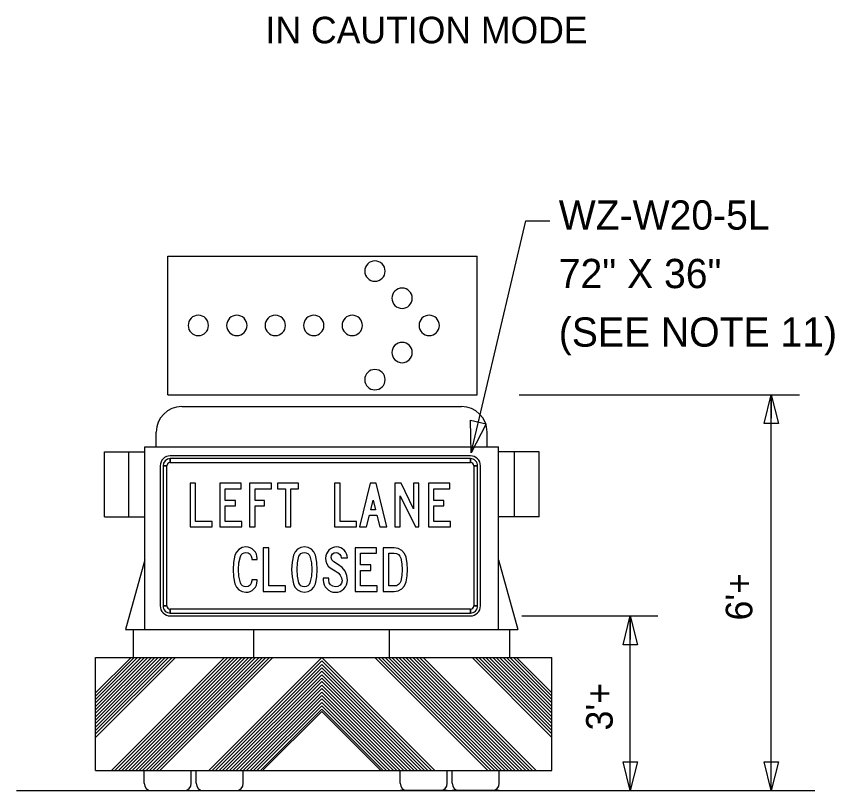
# Model space of a CAD drawing. Extents: x 1806907 to 1812607, y 675071 to 676228.
# Drawn here: x 1811793.7 to 1811978.3, y 675389 to 675563.7 of the extents above; entities that cross this region are included whole.
import ezdxf

# ---------------------------------------------------------------- set-up
doc = ezdxf.new("R2010")
doc.units = 0
doc.layers.add('Working Level 1', color=7, linetype='Continuous')

msp = doc.modelspace()

# ---------------------------------------------------------------- linework, layer by layer
at = {"layer": 'Working Level 1'}
for p, q in [((1811827.84, 675509.6), (1811897.61, 675509.6)), ((1811827.84, 675478.31), (1811827.84, 675509.6)), ((1811897.61, 675478.31), (1811897.61, 675509.6)), ((1811827.84, 675478.31), (1811897.61, 675478.31)), ((1811907.08, 675478.31), (1811970.35, 675478.31)), ((1811963.98, 675389), (1811963.98, 675478.31)), ((1811963.98, 675478.31), (1811963.98, 675473.07)), ((1811830.98, 675475.64), (1811894.12, 675475.64)), ((1811825.24, 675466.6), (1811825.24, 675469.9)), ((1811899.87, 675466.6), (1811899.87, 675469.9)), ((1811822.64, 675425.34), (1811822.64, 675466.6)), ((1811822.64, 675466.6), (1811902.47, 675466.6)), ((1811902.47, 675425.34), (1811902.47, 675466.6)), ((1811813.53, 675465.44), (1811822.64, 675465.44)), ((1811813.53, 675450.77), (1811813.53, 675465.44)), ((1811819.05, 675450.77), (1811819.05, 675465.44)), ((1811896.1, 675464.53), (1811828.38, 675464.53)), ((1811911.58, 675465.44), (1811902.47, 675465.44)), ((1811906.06, 675450.77), (1811906.06, 675465.44)), ((1811911.58, 675450.77), (1811911.58, 675465.44)), ((1811828.38, 675463.03), (1811828.38, 675463.91)), ((1811896.1, 675463.91), (1811896.1, 675463.03)), ((1811826.13, 675462.28), (1811826.13, 675430.68)), ((1811826.75, 675462.28), (1811827.63, 675462.28)), ((1811896.85, 675462.28), (1811897.73, 675462.28)), ((1811898.35, 675430.68), (1811898.35, 675462.28)), ((1811813.53, 675450.77), (1811822.64, 675450.77)), ((1811911.58, 675450.77), (1811902.47, 675450.77)), ((1811822.64, 675441.06), (1811818.32, 675425.34)), ((1811902.47, 675441.06), (1811906.78, 675425.34)), ((1811827.63, 675430.68), (1811826.75, 675430.68)), ((1811828.38, 675429.05), (1811828.38, 675429.92)), ((1811896.1, 675429.92), (1811896.1, 675429.05)), ((1811897.73, 675430.68), (1811896.85, 675430.68)), ((1811828.38, 675428.42), (1811896.1, 675428.42)), ((1811907.73, 675428.42), (1811938.35, 675428.42)), ((1811932.17, 675389), (1811932.17, 675428.42)), ((1811932.17, 675428.42), (1811932.17, 675423.09)), ((1811818.32, 675425.34), (1811906.78, 675425.34)), ((1811820.12, 675419.03), (1811820.12, 675425.34)), ((1811847.24, 675419.03), (1811847.24, 675425.22)), ((1811877.87, 675419.03), (1811877.87, 675425.22)), ((1811904.99, 675419.03), (1811904.99, 675425.34)), ((1811811.55, 675419.03), (1811914.5, 675419.03)), ((1811811.55, 675419.03), (1811914.5, 675419.03)), ((1811811.55, 675419.03), (1811914.5, 675419.03)), ((1811811.55, 675419.03), (1811914.5, 675419.03)), ((1811811.55, 675393.54), (1811811.55, 675419.03)), ((1811811.55, 675411.05), (1811819.53, 675419.03)), ((1811811.55, 675401.78), (1811828.81, 675419.03)), ((1811811.55, 675402.56), (1811828.02, 675419.03)), ((1811811.55, 675403.34), (1811827.24, 675419.03)), ((1811811.55, 675404.11), (1811826.47, 675419.03)), ((1811811.55, 675404.89), (1811825.69, 675419.03)), ((1811811.55, 675405.67), (1811824.91, 675419.03)), ((1811811.55, 675406.44), (1811824.14, 675419.03)), ((1811811.55, 675407.22), (1811823.36, 675419.03)), ((1811811.55, 675408), (1811822.58, 675419.03)), ((1811811.55, 675408.78), (1811821.8, 675419.03)), ((1811811.55, 675409.55), (1811821.03, 675419.03)), ((1811811.55, 675410.33), (1811820.25, 675419.03)), ((1811811.55, 675401), (1811829.56, 675419.01)), ((1811815.14, 675393.54), (1811840.64, 675419.03)), ((1811815.91, 675393.54), (1811841.41, 675419.03)), ((1811816.69, 675393.54), (1811842.19, 675419.03)), ((1811817.48, 675393.54), (1811842.97, 675419.03)), ((1811818.25, 675393.54), (1811843.74, 675419.03)), ((1811819.03, 675393.54), (1811844.52, 675419.03)), ((1811819.81, 675393.54), (1811845.31, 675419.03)), ((1811820.59, 675393.54), (1811846.09, 675419.03)), ((1811821.36, 675393.54), (1811846.86, 675419.03)), ((1811822.14, 675393.54), (1811847.64, 675419.03)), ((1811822.92, 675393.54), (1811848.42, 675419.03)), ((1811823.69, 675393.54), (1811849.19, 675419.03)), ((1811824.47, 675393.54), (1811849.97, 675419.03)), ((1811825.25, 675393.54), (1811850.74, 675419.02)), ((1811826.03, 675393.54), (1811851.53, 675419.03)), ((1811837.06, 675393.54), (1811862.55, 675419.03)), ((1811837.83, 675393.54), (1811862.55, 675418.26)), ((1811888.05, 675393.54), (1811862.55, 675419.03)), ((1811887.24, 675393.58), (1811862.55, 675418.26)), ((1811900.01, 675393.54), (1811874.52, 675419.03)), ((1811900.79, 675393.54), (1811875.3, 675419.02)), ((1811901.57, 675393.54), (1811876.07, 675419.03)), ((1811902.35, 675393.54), (1811876.85, 675419.03)), ((1811903.12, 675393.54), (1811877.62, 675419.03)), ((1811903.9, 675393.54), (1811878.4, 675419.03)), ((1811904.68, 675393.54), (1811879.19, 675419.03)), ((1811905.45, 675393.54), (1811879.96, 675419.03)), ((1811906.23, 675393.54), (1811880.74, 675419.03)), ((1811907.02, 675393.54), (1811881.52, 675419.03)), ((1811907.8, 675393.54), (1811882.3, 675419.03)), ((1811908.57, 675393.54), (1811883.07, 675419.03)), ((1811909.35, 675393.54), (1811883.85, 675419.03)), ((1811910.13, 675393.54), (1811884.63, 675419.03)), ((1811910.9, 675393.54), (1811885.41, 675419.03)), ((1811914.5, 675401), (1811896.48, 675419.01)), ((1811914.5, 675401.78), (1811897.24, 675419.03)), ((1811914.5, 675402.56), (1811898.02, 675419.03)), ((1811914.5, 675403.34), (1811898.8, 675419.03)), ((1811914.5, 675404.11), (1811899.57, 675419.03)), ((1811914.5, 675404.89), (1811900.35, 675419.03)), ((1811914.5, 675405.67), (1811901.13, 675419.03)), ((1811914.5, 675406.44), (1811901.9, 675419.03)), ((1811914.5, 675407.22), (1811902.68, 675419.03)), ((1811914.5, 675408), (1811903.46, 675419.03)), ((1811914.5, 675408.78), (1811904.24, 675419.03)), ((1811914.5, 675409.55), (1811905.01, 675419.03)), ((1811914.5, 675410.33), (1811905.79, 675419.03)), ((1811914.5, 675411.05), (1811906.52, 675419.03)), ((1811914.5, 675393.54), (1811914.5, 675419.03)), ((1811838.61, 675393.54), (1811862.55, 675417.48)), ((1811839.39, 675393.54), (1811862.55, 675416.7)), ((1811886.5, 675393.54), (1811862.55, 675417.48)), ((1811885.72, 675393.54), (1811862.55, 675416.7)), ((1811840.16, 675393.54), (1811862.55, 675415.93)), ((1811840.94, 675393.54), (1811862.55, 675415.15)), ((1811884.95, 675393.54), (1811862.55, 675415.93)), ((1811884.17, 675393.54), (1811862.55, 675415.15)), ((1811841.73, 675393.54), (1811862.55, 675414.37)), ((1811842.5, 675393.54), (1811862.55, 675413.6)), ((1811843.28, 675393.54), (1811862.55, 675412.81)), ((1811883.39, 675393.54), (1811862.55, 675414.37)), ((1811882.62, 675393.54), (1811862.55, 675413.6)), ((1811881.84, 675393.54), (1811862.55, 675412.81)), ((1811844.06, 675393.54), (1811862.55, 675412.03)), ((1811844.84, 675393.54), (1811862.55, 675411.25)), ((1811881.06, 675393.54), (1811862.55, 675412.03)), ((1811880.27, 675393.54), (1811862.55, 675411.25)), ((1811845.61, 675393.54), (1811862.55, 675410.48)), ((1811846.39, 675393.54), (1811862.55, 675409.7)), ((1811879.5, 675393.54), (1811862.55, 675410.48)), ((1811878.72, 675393.54), (1811862.55, 675409.7)), ((1811847.17, 675393.54), (1811862.55, 675408.92)), ((1811847.94, 675393.54), (1811862.55, 675408.15)), ((1811848.72, 675393.54), (1811862.55, 675407.37)), ((1811877.94, 675393.54), (1811862.55, 675408.92)), ((1811877.17, 675393.54), (1811862.55, 675408.15)), ((1811876.39, 675393.54), (1811862.55, 675407.37)), ((1811849.37, 675393.69), (1811862.55, 675406.87)), ((1811875.89, 675393.54), (1811862.55, 675406.87)), ((1811811.55, 675393.54), (1811914.5, 675393.54)), ((1811811.55, 675393.54), (1811914.5, 675393.54)), ((1811811.55, 675393.54), (1811914.5, 675393.54)), ((1811811.55, 675393.54), (1811914.5, 675393.54)), ((1811822.49, 675390.65), (1811822.49, 675393.54)), ((1811833.12, 675390.65), (1811833.12, 675393.54)), ((1811834.22, 675390.65), (1811834.22, 675393.54)), ((1811844.86, 675390.65), (1811844.86, 675393.54)), ((1811880.25, 675390.65), (1811880.25, 675393.54)), ((1811890.88, 675390.65), (1811890.88, 675393.54)), ((1811891.98, 675390.65), (1811891.98, 675393.54)), ((1811902.62, 675390.65), (1811902.62, 675393.54)), ((1811793.67, 675389), (1811973.78, 675389)), ((1811822.49, 675389), (1811833.12, 675389)), ((1811822.49, 675389), (1811833.12, 675389)), ((1811822.49, 675389), (1811833.12, 675389)), ((1811822.49, 675389), (1811833.12, 675389)), ((1811834.22, 675389), (1811844.86, 675389)), ((1811834.22, 675389), (1811844.86, 675389)), ((1811834.22, 675389), (1811844.86, 675389)), ((1811834.22, 675389), (1811844.86, 675389)), ((1811890.88, 675389), (1811880.25, 675389)), ((1811890.88, 675389), (1811880.25, 675389)), ((1811890.88, 675389), (1811880.25, 675389)), ((1811890.88, 675389), (1811880.25, 675389)), ((1811902.62, 675389), (1811891.98, 675389)), ((1811902.62, 675389), (1811891.98, 675389)), ((1811902.62, 675389), (1811891.98, 675389)), ((1811902.62, 675389), (1811891.98, 675389))]:
    msp.add_line(p, q, dxfattribs=at)
for points in [[(1811896.25, 675465.19), (1811908.59, 675517.59), (1811913.99, 675517.59)], [(1811877.26, 675448.48), (1811874.85, 675458.34), (1811873.45, 675458.34), (1811871.05, 675448.48), (1811872.68, 675448.48), (1811873.32, 675451.12), (1811874.98, 675451.12), (1811875.63, 675448.48), (1811877.26, 675448.48)], [(1811874.68, 675452.35), (1811873.62, 675452.35), (1811874.15, 675454.52), (1811874.68, 675452.35)], [(1811861.56, 675438.87), (1811861.45, 675440.52), (1811861.12, 675442.13), (1811860.78, 675442.86), (1811860.21, 675443.45), (1811859.48, 675443.84), (1811858.66, 675443.97), (1811857.83, 675443.84), (1811857.1, 675443.45), (1811856.53, 675442.85), (1811856.18, 675442.12), (1811855.86, 675440.51), (1811855.75, 675438.87), (1811855.86, 675437.24), (1811856.18, 675435.63), (1811856.52, 675434.89), (1811857.09, 675434.29), (1811857.83, 675433.89), (1811858.66, 675433.76), (1811859.49, 675433.89), (1811860.22, 675434.29), (1811860.79, 675434.89), (1811861.13, 675435.64), (1811861.45, 675437.24), (1811861.56, 675438.87)], [(1811860.33, 675438.86), (1811860.22, 675437.35), (1811859.9, 675435.86), (1811859.73, 675435.51), (1811859.44, 675435.23), (1811859.07, 675435.05), (1811858.66, 675434.99), (1811858.24, 675435.05), (1811857.87, 675435.24), (1811857.58, 675435.52), (1811857.41, 675435.87), (1811857.09, 675437.35), (1811856.99, 675438.86), (1811857.09, 675440.38), (1811857.41, 675441.87), (1811857.58, 675442.22), (1811857.87, 675442.49), (1811858.24, 675442.68), (1811858.66, 675442.74), (1811859.07, 675442.68), (1811859.44, 675442.49), (1811859.73, 675442.22), (1811859.9, 675441.88), (1811860.22, 675440.39), (1811860.33, 675438.86)], [(1811876.45, 675433.94), (1811878.86, 675433.94), (1811879.79, 675434.09), (1811880.61, 675434.54), (1811881.23, 675435.23), (1811881.59, 675436.08), (1811881.83, 675437.45), (1811881.91, 675438.86), (1811881.83, 675440.27), (1811881.59, 675441.65), (1811881.23, 675442.5), (1811880.61, 675443.18), (1811879.79, 675443.64), (1811878.86, 675443.79), (1811876.45, 675443.79), (1811876.45, 675433.94)], [(1811877.69, 675435.17), (1811877.69, 675442.56), (1811878.89, 675442.56), (1811879.39, 675442.48), (1811879.84, 675442.25), (1811880.18, 675441.89), (1811880.38, 675441.45), (1811880.6, 675440.17), (1811880.68, 675438.86), (1811880.6, 675437.55), (1811880.38, 675436.28), (1811880.18, 675435.84), (1811879.84, 675435.48), (1811879.39, 675435.24), (1811878.89, 675435.17), (1811877.69, 675435.17)]]:
    msp.add_lwpolyline(points, dxfattribs=at)
for points in [[(1811962.36, 675471.81), (1811963.98, 675478.31), (1811965.61, 675471.81)], [(1811899.63, 675471.74), (1811896.25, 675465.19), (1811896.15, 675472.56)], [(1811896.1, 675463.91), (1811828.38, 675463.91), (1811828.38, 675463.03), (1811896.1, 675463.03), (1811896.1, 675463.91)], [(1811826.75, 675462.28), (1811826.75, 675430.68), (1811827.63, 675430.68), (1811827.63, 675462.28), (1811826.75, 675462.28)], [(1811897.73, 675430.68), (1811897.73, 675462.28), (1811896.85, 675462.28), (1811896.85, 675430.68), (1811897.73, 675430.68)], [(1811837.82, 675448.48), (1811837.82, 675449.71), (1811834.09, 675449.71), (1811834.09, 675458.34), (1811832.85, 675458.34), (1811832.85, 675448.48)], [(1811844.53, 675448.48), (1811844.53, 675449.71), (1811840.8, 675449.71), (1811840.8, 675453.23), (1811843.08, 675453.23), (1811843.08, 675454.47), (1811840.8, 675454.47), (1811840.8, 675457.11), (1811844.37, 675457.11), (1811844.37, 675458.34), (1811839.56, 675458.34), (1811839.56, 675448.48)], [(1811851.24, 675457.11), (1811851.24, 675458.34), (1811846.27, 675458.34), (1811846.27, 675448.48), (1811847.51, 675448.48), (1811847.51, 675453.23), (1811849.62, 675453.23), (1811849.62, 675454.47), (1811847.51, 675454.47), (1811847.51, 675457.11)], [(1811857.35, 675457.11), (1811857.35, 675458.34), (1811852.6, 675458.34), (1811852.6, 675457.11), (1811854.36, 675457.11), (1811854.36, 675448.48), (1811855.59, 675448.48), (1811855.59, 675457.11)], [(1811870.43, 675448.48), (1811870.43, 675449.71), (1811866.7, 675449.71), (1811866.7, 675458.34), (1811865.47, 675458.34), (1811865.47, 675448.48)], [(1811884.47, 675448.48), (1811884.47, 675458.34), (1811883.24, 675458.34), (1811883.24, 675452.59), (1811880.44, 675458.34), (1811879.01, 675458.34), (1811879.01, 675448.48), (1811880.25, 675448.48), (1811880.25, 675455.53), (1811883.68, 675448.48)], [(1811891.58, 675448.48), (1811891.58, 675449.71), (1811887.84, 675449.71), (1811887.84, 675453.23), (1811890.13, 675453.23), (1811890.13, 675454.47), (1811887.84, 675454.47), (1811887.84, 675457.11), (1811891.42, 675457.11), (1811891.42, 675458.34), (1811886.61, 675458.34), (1811886.61, 675448.48)], [(1811848, 675436.58), (1811846.76, 675436.58), (1811846.76, 675436.3), (1811846.67, 675435.8), (1811846.38, 675435.37), (1811845.96, 675435.09), (1811845.46, 675434.99), (1811845.04, 675435.05), (1811844.66, 675435.24), (1811844.37, 675435.52), (1811844.2, 675435.87), (1811843.88, 675437.35), (1811843.77, 675438.86), (1811843.88, 675440.37), (1811844.2, 675441.85), (1811844.37, 675442.2), (1811844.66, 675442.49), (1811845.04, 675442.67), (1811845.46, 675442.74), (1811845.96, 675442.64), (1811846.38, 675442.35), (1811846.67, 675441.93), (1811846.76, 675441.43), (1811846.76, 675441.15), (1811848, 675441.15), (1811848, 675441.4), (1811847.95, 675441.91), (1811847.81, 675442.38), (1811847.58, 675442.82), (1811847.25, 675443.21), (1811846.85, 675443.54), (1811846.42, 675443.78), (1811845.95, 675443.92), (1811845.43, 675443.97), (1811844.6, 675443.83), (1811843.87, 675443.44), (1811843.3, 675442.83), (1811842.96, 675442.09), (1811842.65, 675440.48), (1811842.54, 675438.87), (1811842.65, 675437.22), (1811842.97, 675435.63), (1811843.31, 675434.88), (1811843.88, 675434.29), (1811844.61, 675433.89), (1811845.43, 675433.76), (1811845.95, 675433.81), (1811846.42, 675433.95), (1811846.85, 675434.18), (1811847.25, 675434.51), (1811847.58, 675434.91), (1811847.81, 675435.34), (1811847.95, 675435.81), (1811848, 675436.33)], [(1811854.35, 675433.94), (1811854.35, 675435.17), (1811850.61, 675435.17), (1811850.61, 675443.79), (1811849.38, 675443.79), (1811849.38, 675433.94)], [(1811862.91, 675436.93), (1811862.91, 675436.52), (1811862.96, 675435.97), (1811863.11, 675435.46), (1811863.35, 675434.99), (1811863.71, 675434.57), (1811864.12, 675434.21), (1811864.58, 675433.96), (1811865.09, 675433.81), (1811865.63, 675433.76), (1811866.18, 675433.81), (1811866.68, 675433.96), (1811867.14, 675434.21), (1811867.57, 675434.56), (1811867.91, 675434.98), (1811868.16, 675435.44), (1811868.31, 675435.94), (1811868.36, 675436.49), (1811868.22, 675437.54), (1811867.81, 675438.51), (1811867.18, 675439.33), (1811866.36, 675439.96), (1811865.29, 675440.64), (1811864.82, 675441.04), (1811864.67, 675441.61), (1811864.75, 675442.04), (1811865, 675442.4), (1811865.36, 675442.65), (1811865.79, 675442.74), (1811866.22, 675442.64), (1811866.58, 675442.37), (1811866.83, 675441.97), (1811866.91, 675441.5), (1811868.36, 675441.5), (1811868.32, 675441.99), (1811868.18, 675442.45), (1811867.95, 675442.86), (1811867.64, 675443.24), (1811867.26, 675443.56), (1811866.84, 675443.79), (1811866.39, 675443.92), (1811865.9, 675443.97), (1811865.4, 675443.92), (1811864.95, 675443.78), (1811864.53, 675443.55), (1811864.15, 675443.22), (1811863.84, 675442.83), (1811863.61, 675442.41), (1811863.48, 675441.94), (1811863.44, 675441.43), (1811863.5, 675440.75), (1811863.7, 675440.16), (1811864.02, 675439.66), (1811864.48, 675439.25), (1811865.56, 675438.6), (1811866.25, 675438.16), (1811866.74, 675437.64), (1811867.03, 675437.02), (1811867.13, 675436.32), (1811867.02, 675435.81), (1811866.69, 675435.38), (1811866.2, 675435.09), (1811865.63, 675434.99), (1811865.05, 675435.1), (1811864.57, 675435.43), (1811864.25, 675435.91), (1811864.14, 675436.49), (1811864.14, 675436.93)], [(1811875.05, 675433.94), (1811875.05, 675435.17), (1811871.32, 675435.17), (1811871.32, 675438.69), (1811873.6, 675438.69), (1811873.6, 675439.92), (1811871.32, 675439.92), (1811871.32, 675442.56), (1811874.89, 675442.56), (1811874.89, 675443.79), (1811870.08, 675443.79), (1811870.08, 675433.94)], [(1811828.38, 675429.05), (1811896.1, 675429.05), (1811896.1, 675429.92), (1811828.38, 675429.92), (1811828.38, 675429.05)], [(1811930.55, 675421.92), (1811932.17, 675428.42), (1811933.8, 675421.92)], [(1811933.8, 675395.5), (1811932.17, 675389), (1811930.55, 675395.5)], [(1811965.61, 675395.5), (1811963.98, 675389), (1811962.36, 675395.5)]]:
    msp.add_lwpolyline(points, close=True, dxfattribs=at)
for centre, radius, start, end in [((1811874.56, 675506.22), 2.3, 0, 180), ((1811874.56, 675506.22), 2.3, 180, 0), ((1811880.68, 675500.09), 2.3, 0, 180), ((1811880.68, 675500.09), 2.3, 180, 0), ((1811834.72, 675493.96), 2.3, 0, 180), ((1811843.4, 675493.96), 2.3, 0, 180), ((1811852.08, 675493.96), 2.3, 0, 180), ((1811860.76, 675493.96), 2.3, 0, 180), ((1811869.44, 675493.96), 2.3, 0, 180), ((1811886.8, 675493.96), 2.3, 0, 180), ((1811834.72, 675493.96), 2.3, 180, 0), ((1811843.4, 675493.96), 2.3, 180, 0), ((1811852.08, 675493.96), 2.3, 180, 0), ((1811860.76, 675493.96), 2.3, 180, 0), ((1811869.44, 675493.96), 2.3, 180, 0), ((1811886.8, 675493.96), 2.3, 180, 0), ((1811880.68, 675487.84), 2.3, 0, 180), ((1811880.68, 675487.84), 2.3, 180, 0), ((1811874.56, 675481.72), 2.3, 0, 180), ((1811874.56, 675481.72), 2.3, 180, 0), ((1811830.98, 675469.9), 5.74, 90, 180), ((1811894.12, 675469.9), 5.74, 0, 90), ((1811828.38, 675462.28), 2.26, 90.0002, 179.9998), ((1811896.1, 675462.28), 2.26, 0, 90.0002), ((1811828.38, 675462.28), 1.63, 90.0002, 179.9998), ((1811828.38, 675462.28), 0.752, 90.0002, 179.9998), ((1811896.1, 675462.28), 1.63, 0, 90.0002), ((1811896.1, 675462.28), 0.752, 0, 90.0002), ((1811828.38, 675430.68), 2.26, 179.9998, 270.0001), ((1811828.38, 675430.68), 1.63, 179.9998, 270.0001), ((1811828.38, 675430.68), 0.752, 179.9998, 270.0001), ((1811896.1, 675430.68), 2.26, 270.0001, 0.0003), ((1811896.1, 675430.68), 1.63, 270.0001, 0.0003), ((1811896.1, 675430.68), 0.752, 270.0001, 0.0003), ((1811824.14, 675390.65), 1.65, 180, 270), ((1811831.47, 675390.65), 1.65, 270, 0), ((1811835.87, 675390.65), 1.65, 180, 270), ((1811843.21, 675390.65), 1.65, 270, 0), ((1811881.9, 675390.65), 1.65, 180, 270), ((1811889.23, 675390.65), 1.65, 270, 0), ((1811893.63, 675390.65), 1.65, 180, 270), ((1811900.97, 675390.65), 1.65, 270, 0)]:
    msp.add_arc(centre, radius, start, end, dxfattribs=at)

# ---------------------------------------------------------------- texts
for s, height, p in [('IN CAUTION MODE', 6, (1811849.88, 675557.6)), ('WZ-W20-5L', 6.6, (1811916.03, 675515.57)), ('72" X 36"', 6.6, (1811916.03, 675502.37)), ('(SEE NOTE 11)', 6.6, (1811916.03, 675489.17))]:
    msp.add_text(s, height=height, dxfattribs=at).set_placement(p)
for s, p in [("6'+", (1811959.69, 675427.4)), ("3'+", (1811928.19, 675402.59))]:
    msp.add_text(s, height=6, rotation=90, dxfattribs=at).set_placement(p)

doc.saveas('drawing.dxf')
